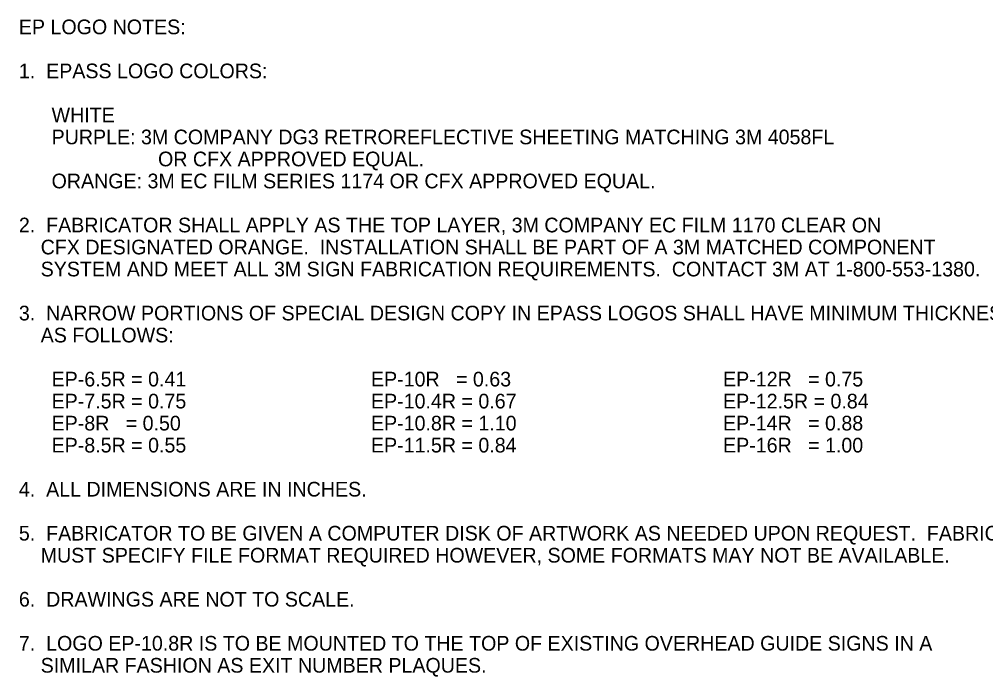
# Model space of a CAD drawing. Extents: x 10268197 to 10269179, y 2141503 to 2142677.
# Drawn here: x 10268659.65 to 10268705.76, y 2142090.52 to 2142121.88 of the extents above; entities that cross this region are included whole.
import ezdxf

# ---------------------------------------------------------------- set-up
doc = ezdxf.new("R2010")
doc.units = 0
doc.layers.add('TextNotes', color=7, linetype='Continuous')

msp = doc.modelspace()

# ---------------------------------------------------------------- texts
at = {"layer": 'TextNotes'}
for s, p in [('EP LOGO NOTES:', (10268659.632, 2142121.167)), ('1.  EPASS LOGO COLORS:', (10268659.632, 2142119.067)), ('      WHITE', (10268659.632, 2142116.967)), ('      PURPLE: 3M COMPANY DG3 RETROREFLECTIVE SHEETING MATCHING 3M 4058FL ', (10268659.632, 2142115.917)), ('    OR CFX APPROVED EQUAL.', (10268665.232, 2142114.867)), ('      ORANGE: 3M EC FILM SERIES 1174 OR CFX APPROVED EQUAL.', (10268659.632, 2142113.817)), ('2.  FABRICATOR SHALL APPLY AS THE TOP LAYER, 3M COMPANY EC FILM 1170 CLEAR ON', (10268659.632, 2142111.717)), ('    CFX DESIGNATED ORANGE.  INSTALLATION SHALL BE PART OF A 3M MATCHED COMPONENT', (10268659.632, 2142110.667)), ('    SYSTEM AND MEET ALL 3M SIGN FABRICATION REQUIREMENTS.  CONTACT 3M AT 1-800-553-1380.', (10268659.632, 2142109.617)), ('3.  NARROW PORTIONS OF SPECIAL DESIGN COPY IN EPASS LOGOS SHALL HAVE MINIMUM THICKNESS', (10268659.632, 2142107.517)), ('    AS FOLLOWS:', (10268659.632, 2142106.467)), ('      EP-6.5R = 0.41', (10268659.632, 2142104.367)), ('EP-10R   = 0.63', (10268676.432, 2142104.367)), ('EP-12R   = 0.75', (10268693.232, 2142104.367)), ('      EP-7.5R = 0.75', (10268659.632, 2142103.317)), ('EP-10.4R = 0.67', (10268676.432, 2142103.317)), ('EP-12.5R = 0.84', (10268693.232, 2142103.317)), ('      EP-8R   = 0.50', (10268659.632, 2142102.267)), ('EP-10.8R = 1.10', (10268676.432, 2142102.267)), ('EP-14R   = 0.88', (10268693.232, 2142102.267)), ('      EP-8.5R = 0.55', (10268659.632, 2142101.217)), ('EP-11.5R = 0.84', (10268676.432, 2142101.217)), ('EP-16R   = 1.00', (10268693.232, 2142101.217)), ('4.  ALL DIMENSIONS ARE IN INCHES.', (10268659.632, 2142099.117)), ('5.  FABRICATOR TO BE GIVEN A COMPUTER DISK OF ARTWORK AS NEEDED UPON REQUEST.  FABRICATOR', (10268659.632, 2142097.017)), ('    MUST SPECIFY FILE FORMAT REQUIRED HOWEVER, SOME FORMATS MAY NOT BE AVAILABLE.', (10268659.632, 2142095.967)), ('6.  DRAWINGS ARE NOT TO SCALE.', (10268659.632, 2142093.867)), ('7.  LOGO EP-10.8R IS TO BE MOUNTED TO THE TOP OF EXISTING OVERHEAD GUIDE SIGNS IN A', (10268659.632, 2142091.767)), ('    SIMILAR FASHION AS EXIT NUMBER PLAQUES.', (10268659.632, 2142090.717))]:
    msp.add_text(s, height=0.7, dxfattribs=at).set_placement(p)

doc.saveas('drawing.dxf')
